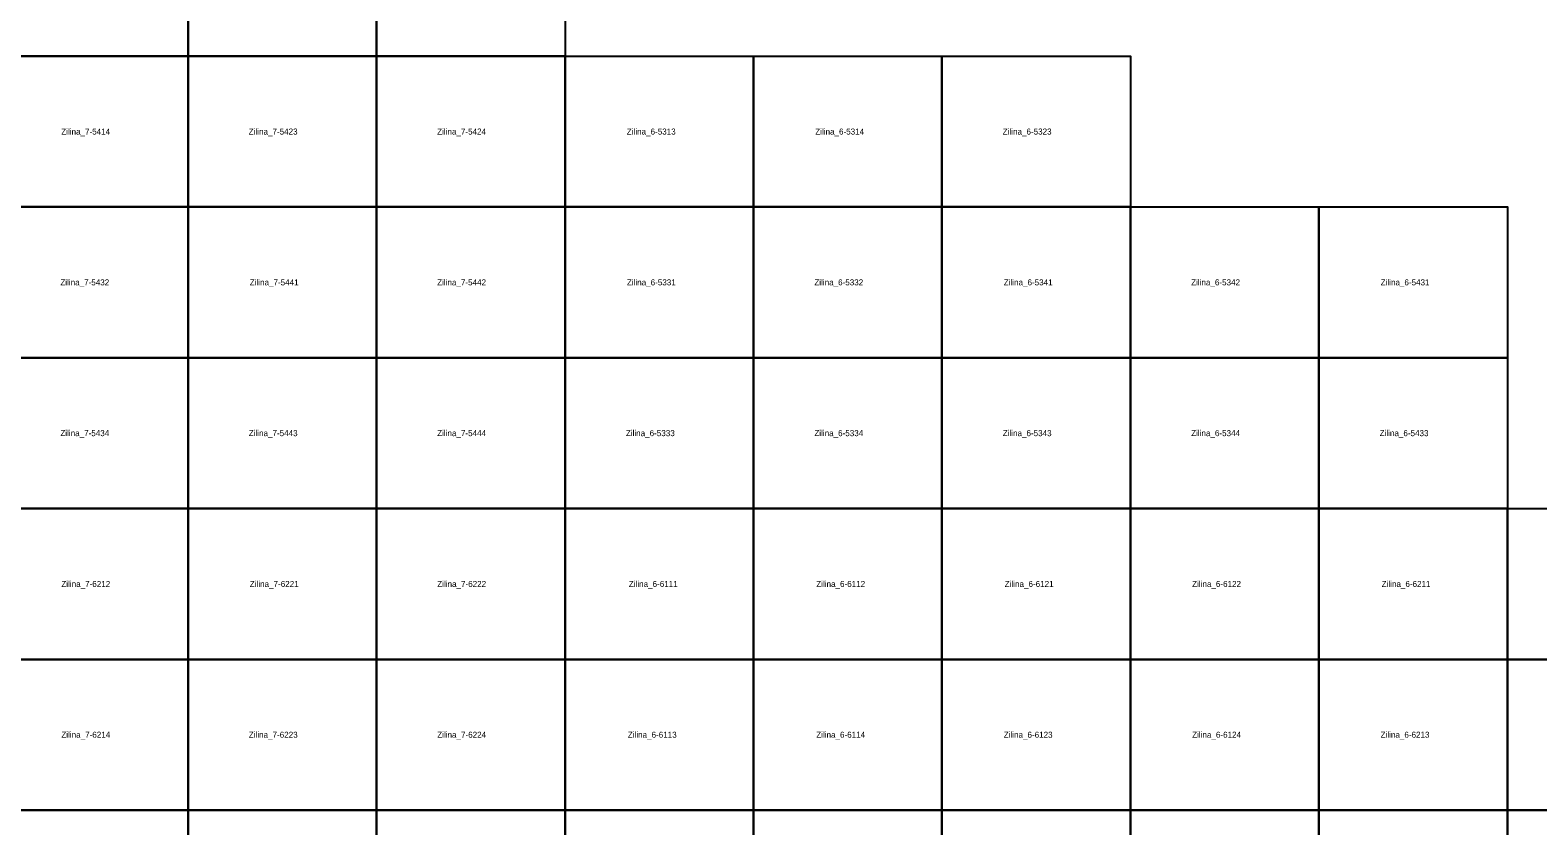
# Model space of a CAD drawing. Extents: x -445938 to -437812, y -1177250 to -1169500.
# Drawn here: x -443387 to -440887, y -1172526 to -1171207 of the extents above; entities that cross this region are included whole.
import ezdxf

# ---------------------------------------------------------------- set-up
doc = ezdxf.new("R2010")
doc.units = 0
for name, color, linetype in [('Vrstva 1', 7, 'Continuous'), ('Vrstva 4', 7, 'Continuous'), ('Vrstva 6', 7, 'Continuous')]:
    doc.layers.add(name, color=color, linetype=linetype)

msp = doc.modelspace()

# ---------------------------------------------------------------- linework, layer by layer
at = {"layer": 'Vrstva 1'}
msp.add_lwpolyline([(-440000, -1170750), (-442500, -1170750), (-442500, -1171250), (-441562.5, -1171250), (-441562.5, -1171500), (-440937.5, -1171500), (-440937.5, -1172000), (-440625, -1172000)], dxfattribs=at)
at = {"layer": 'Vrstva 4'}
for points in [[(-443125, -1171000), (-443125, -1171250), (-443437.5, -1171250), (-443437.5, -1171000)], [(-442812.5, -1171000), (-442812.5, -1171250), (-443125, -1171250), (-443125, -1171000)], [(-442500, -1171000), (-442500, -1171250), (-442812.5, -1171250), (-442812.5, -1171000)], [(-443125, -1171250), (-443125, -1171500), (-443437.5, -1171500), (-443437.5, -1171250)], [(-442812.5, -1171250), (-442812.5, -1171500), (-443125, -1171500), (-443125, -1171250)], [(-442500, -1171250), (-442500, -1171500), (-442812.5, -1171500), (-442812.5, -1171250)], [(-442187.5, -1171250), (-442187.5, -1171500), (-442500, -1171500), (-442500, -1171250)], [(-441875, -1171250), (-441875, -1171500), (-442187.5, -1171500), (-442187.5, -1171250)], [(-441562.5, -1171250), (-441562.5, -1171500), (-441875, -1171500), (-441875, -1171250)], [(-443125, -1171500), (-443125, -1171750), (-443437.5, -1171750), (-443437.5, -1171500)], [(-442812.5, -1171500), (-442812.5, -1171750), (-443125, -1171750), (-443125, -1171500)], [(-442500, -1171500), (-442500, -1171750), (-442812.5, -1171750), (-442812.5, -1171500)], [(-442187.5, -1171500), (-442187.5, -1171750), (-442500, -1171750), (-442500, -1171500)], [(-441875, -1171500), (-441875, -1171750), (-442187.5, -1171750), (-442187.5, -1171500)], [(-441562.5, -1171500), (-441562.5, -1171750), (-441875, -1171750), (-441875, -1171500)], [(-441250, -1171500), (-441250, -1171750), (-441562.5, -1171750), (-441562.5, -1171500)], [(-440937.5, -1171500), (-440937.5, -1171750), (-441250, -1171750), (-441250, -1171500)], [(-443125, -1171750), (-443125, -1172000), (-443437.5, -1172000), (-443437.5, -1171750)], [(-442812.5, -1171750), (-442812.5, -1172000), (-443125, -1172000), (-443125, -1171750)], [(-442500, -1171750), (-442500, -1172000), (-442812.5, -1172000), (-442812.5, -1171750)], [(-442187.5, -1171750), (-442187.5, -1172000), (-442500, -1172000), (-442500, -1171750)], [(-441875, -1171750), (-441875, -1172000), (-442187.5, -1172000), (-442187.5, -1171750)], [(-441562.5, -1171750), (-441562.5, -1172000), (-441875, -1172000), (-441875, -1171750)], [(-441250, -1171750), (-441250, -1172000), (-441562.5, -1172000), (-441562.5, -1171750)], [(-440937.5, -1171750), (-440937.5, -1172000), (-441250, -1172000), (-441250, -1171750)], [(-443125, -1172000), (-443125, -1172250), (-443437.5, -1172250), (-443437.5, -1172000)], [(-442812.5, -1172000), (-442812.5, -1172250), (-443125, -1172250), (-443125, -1172000)], [(-442500, -1172000), (-442500, -1172250), (-442812.5, -1172250), (-442812.5, -1172000)], [(-442187.5, -1172000), (-442187.5, -1172250), (-442500, -1172250), (-442500, -1172000)], [(-441875, -1172000), (-441875, -1172250), (-442187.5, -1172250), (-442187.5, -1172000)], [(-441562.5, -1172000), (-441562.5, -1172250), (-441875, -1172250), (-441875, -1172000)], [(-441250, -1172000), (-441250, -1172250), (-441562.5, -1172250), (-441562.5, -1172000)], [(-440937.5, -1172000), (-440937.5, -1172250), (-441250, -1172250), (-441250, -1172000)], [(-440625, -1172000), (-440625, -1172250), (-440937.5, -1172250), (-440937.5, -1172000)], [(-443125, -1172250), (-443125, -1172500), (-443437.5, -1172500), (-443437.5, -1172250)], [(-442812.5, -1172250), (-442812.5, -1172500), (-443125, -1172500), (-443125, -1172250)], [(-442500, -1172250), (-442500, -1172500), (-442812.5, -1172500), (-442812.5, -1172250)], [(-442187.5, -1172250), (-442187.5, -1172500), (-442500, -1172500), (-442500, -1172250)], [(-441875, -1172250), (-441875, -1172500), (-442187.5, -1172500), (-442187.5, -1172250)], [(-441562.5, -1172250), (-441562.5, -1172500), (-441875, -1172500), (-441875, -1172250)], [(-441250, -1172250), (-441250, -1172500), (-441562.5, -1172500), (-441562.5, -1172250)], [(-440937.5, -1172250), (-440937.5, -1172500), (-441250, -1172500), (-441250, -1172250)], [(-440625, -1172250), (-440625, -1172500), (-440937.5, -1172500), (-440937.5, -1172250)], [(-443125, -1172500), (-443125, -1172750), (-443437.5, -1172750), (-443437.5, -1172500)], [(-442812.5, -1172500), (-442812.5, -1172750), (-443125, -1172750), (-443125, -1172500)], [(-442500, -1172500), (-442500, -1172750), (-442812.5, -1172750), (-442812.5, -1172500)], [(-442187.5, -1172500), (-442187.5, -1172750), (-442500, -1172750), (-442500, -1172500)], [(-441875, -1172500), (-441875, -1172750), (-442187.5, -1172750), (-442187.5, -1172500)], [(-441562.5, -1172500), (-441562.5, -1172750), (-441875, -1172750), (-441875, -1172500)], [(-441250, -1172500), (-441250, -1172750), (-441562.5, -1172750), (-441562.5, -1172500)], [(-440937.5, -1172500), (-440937.5, -1172750), (-441250, -1172750), (-441250, -1172500)], [(-440625, -1172500), (-440625, -1172750), (-440937.5, -1172750), (-440937.5, -1172500)]]:
    msp.add_lwpolyline(points, close=True, dxfattribs=at)

# ---------------------------------------------------------------- texts
at = {"layer": 'Vrstva 6'}
for s, p in [('Zilina_7-5414', (-443335.379, -1171380)), ('Zilina_7-5423', (-443024.572, -1171380)), ('Zilina_7-5424', (-442712.072, -1171380)), ('Zilina_6-5313', (-442397.604, -1171380)), ('Zilina_6-5314', (-442085.104, -1171380)), ('Zilina_6-5323', (-441774.296, -1171380)), ('Zilina_7-5432', (-443336.914, -1171630)), ('Zilina_7-5441', (-443022.878, -1171630)), ('Zilina_7-5442', (-442712.072, -1171630)), ('Zilina_6-5331', (-442397.446, -1171630)), ('Zilina_6-5332', (-442086.638, -1171630)), ('Zilina_6-5341', (-441772.603, -1171630)), ('Zilina_6-5342', (-441461.796, -1171630)), ('Zilina_6-5431', (-441147.603, -1171630)), ('Zilina_7-5434', (-443336.914, -1171880)), ('Zilina_7-5443', (-443024.572, -1171880)), ('Zilina_7-5444', (-442712.072, -1171880)), ('Zilina_6-5333', (-442399.138, -1171880)), ('Zilina_6-5334', (-442086.638, -1171880)), ('Zilina_6-5343', (-441774.296, -1171880)), ('Zilina_6-5344', (-441461.796, -1171880)), ('Zilina_6-5433', (-441149.296, -1171880)), ('Zilina_7-6212', (-443335.261, -1172130)), ('Zilina_7-6221', (-443022.76, -1172130)), ('Zilina_7-6222', (-442711.954, -1172130)), ('Zilina_6-6111', (-442394.258, -1172130)), ('Zilina_6-6112', (-442083.451, -1172130)), ('Zilina_6-6121', (-441770.95, -1172130)), ('Zilina_6-6122', (-441460.144, -1172130)), ('Zilina_6-6211', (-441145.95, -1172130)), ('Zilina_7-6214', (-443335.261, -1172380)), ('Zilina_7-6223', (-443024.454, -1172380)), ('Zilina_7-6224', (-442711.954, -1172380)), ('Zilina_6-6113', (-442395.951, -1172380)), ('Zilina_6-6114', (-442083.451, -1172380)), ('Zilina_6-6123', (-441772.644, -1172380)), ('Zilina_6-6124', (-441460.144, -1172380)), ('Zilina_6-6213', (-441147.644, -1172380))]:
    msp.add_text(s, height=10, dxfattribs=at).set_placement(p)

doc.saveas('drawing.dxf')
